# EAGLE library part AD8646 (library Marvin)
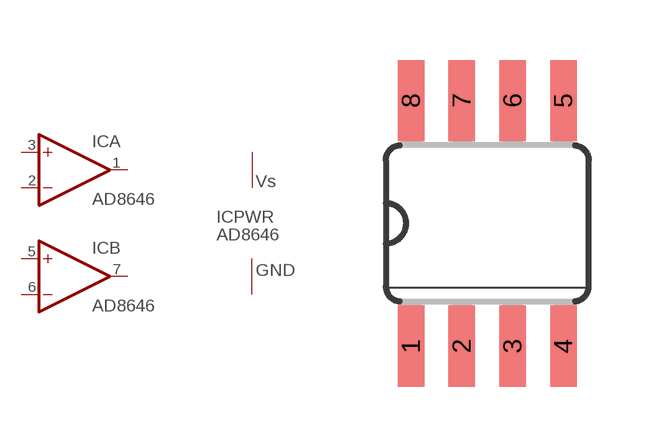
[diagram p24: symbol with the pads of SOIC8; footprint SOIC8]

Designator prefix IC; gates A=OP B=OP PWR=PWR

## AD8646  [SOIC8]
1  A:OUT  out
2  A:-IN  in
3  A:+IN  in
4  PWR:GND  pwr
5  B:+IN  in
6  B:-IN  in
7  B:OUT  out
8  PWR:VS  pwr

## Footprint SOIC8 (pad centres in mm)
smd 0.66 x 2.032: 1 -1.905,-3.073; 2 -0.635,-3.073; 3 0.635,-3.073; 4 1.905,-3.073; 5 1.905,3.073; 6 0.635,3.073; 7 -0.635,3.073; 8 -1.905,3.073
